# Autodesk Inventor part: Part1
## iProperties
Shininess: 64.0
Length Units: 11269
Angle Units: 11279
Time Units: 11290
Mass Units: 11283
Length Display Precision: 3
Angle Display Precision: 2
Created: 2002-07
Part Number: Part1
Document SubType Name: Modeling
Designer: Administrator
Density: 0.0
Volumn: 0.0
Area: 0.0
PropertySet Name: Model Information
Control State: 0
Master: False
Checked Out: False
Author: Administrator
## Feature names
1. Extrusion1
